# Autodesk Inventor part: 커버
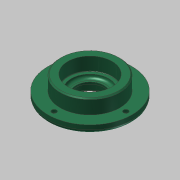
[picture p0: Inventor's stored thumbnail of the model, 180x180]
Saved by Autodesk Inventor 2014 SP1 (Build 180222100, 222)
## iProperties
Company: 한국ATC센터
Created: 2016-04
Part Number: 커버
Document SubType Name: Modeling
Designer: mdu
Density: 7.86 g/cm^3
Mass: 351.567 g
Surface Area: 161.165 cm^2
Volume: 44.7286 cm^3
Material: 강철, 연강
Appearance: 강철
Author: mdu
Revision Number: 1
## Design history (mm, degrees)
sketch "스케치1"
  geometry: C1 r 38 at (0, 0); 1 further point
  constraints: 1 centre point, 1 coincident
  dimensions: "d0" = 76 diameter of C1
extrude "돌출1" new body sketch "스케치1" distance "d1" = 7; taper "d2" = 0 deg
sketch "스케치2"
  geometry: C1 r 27 at (0, 0); 1 further point
  constraints: 1 centre point, 1 coincident
  dimensions: "d3" = 54 diameter of C1
extrude "돌출2" join sketch "스케치2" distance "d4" = 13; taper "d5" = 0 deg
sketch "스케치3"
  geometry: C1 r 20 at (0, 0); 1 further point
  constraints: 1 centre point, 1 coincident
  dimensions: "d6" = 40 diameter of C1
extrude "돌출3" join sketch "스케치3" distance "d7" = 5; taper "d8" = 0 deg
hole "구멍1" diameter "d11" = 25; stored, may be unused: countersink angle "d15" = 90 deg, drill point angle "d17" = 118 deg; dims "d9" = 10, "d10" = 10, "d12" = 6, "d13" = 32, "d14" = 8.3, "d16" = 8
hole "구멍2" diameter "d20" = 34; stored, may be unused: countersink angle "d24" = 90 deg, drill point angle "d26" = 0 deg; dims "d18" = 10, "d19" = 10, "d21" = 6, "d22" = 40, "d23" = 12, "d25" = 3
fillet "모깎기2" dims "d34" = 3
fillet "모깎기1" dims "d27" = 0.3
chamfer "모따기1" distance "d28" = 1; stored, may be unused: second distance "d29" = 2, angle "d30" = 45 deg
chamfer "모따기2" distance "d31" = 1.2; stored, may be unused: second distance "d32" = 2, angle "d33" = 30 deg
sketch "스케치4" dims "d35" = 65
  geometry: 3 further points
  constraints: 2 horizontal alignment, 1 coincident, 2 other
hole "구멍3" sketch "스케치4" at (32.5, 0) diameter "d36" = 4.5; stored, may be unused: countersink angle "d40" = 90 deg, drill point angle "d42" = 118 deg; dims "d37" = 6, "d38" = 8, "d39" = 4.4, "d41" = 13
node "솔리드1"
pattern_circular "원형 패턴1" dims angle "d44" = 360 deg
